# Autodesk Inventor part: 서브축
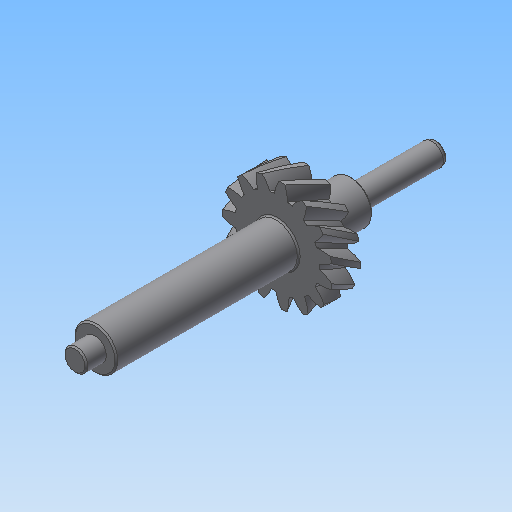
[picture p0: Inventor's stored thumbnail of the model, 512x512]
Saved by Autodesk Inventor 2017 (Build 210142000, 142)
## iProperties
Created: 2016-12
Part Number: 서브축
Material: 강철, 탄소
Document SubType Name: Modeling
Designer: mduedu
Categories: <?xml version="1.0" encoding="UTF-16"?> <MemberInstance><Categories><FamilyTemplate><FamilyTemplateParameter ValueType="xs:double" Id="1" ObjectReferenceKey="da
Density: 7.87 g/cm^3
Appearance: 기본값
Mass: 199.332 g
Surface Area: 86.8151 cm^2
Volume: 25.3281 cm^3
CustomPartVersion: 1
Author: mduedu
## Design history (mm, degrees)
sketch "Sketch1"
  geometry: C1 r 19.321 at (0, 0)
  constraints: 1 centre point
  dimensions: "d0" = 38.64102 diameter of C1 (= da_da)
extrude "Extrusion1" new body sketch "Sketch1" distance "d1" = 10 (= da_b); taper "d2" = 0 deg
workplane "Work Plane2"
sketch "Sketch2"
  geometry: C1 r 19.321 at (0, 0) reference; C2 r 17.321 at (0, 0)
  constraints: 1 centre point, 1 coincident
  dimensions: "d3" = 34.64102 diameter of C2 (= da_dw)
feature "피치 지름" sketch "Sketch2" dims "d4" = 10, "d5" = 0
workplane "Work Plane8"
workplane "Work Plane9"
feature "스퍼 기어" dims "d39" = 0, "da_b" = 10, "da_d" = 34.64102, "da_aw" = 43.87862, "da_da" = 38.64102, "da_df" = 29.64102, "da_dw" = 34.64102, angle "da_beta" = 30 deg, "da_lefttooth" = 0, "da_righttooth" = 10
sketch "스케치3"
  geometry: C1 r 7.5 at (0, 0); 1 further point
  constraints: 1 centre point, 1 coincident
  dimensions: "d49" = 15 diameter of C1
extrude "돌출2" join sketch "스케치3" distance "d50" = 64; taper "d51" = 0 deg
sketch "스케치4"
  geometry: C1 r 4 at (0, 0); 1 further point
  constraints: 1 centre point, 1 coincident
  dimensions: "d52" = 8 diameter of C1
extrude "돌출3" join sketch "스케치4" distance "d53" = 7; taper "d54" = 0 deg
sketch "스케치5"
  geometry: C1 r 7.5 at (0, 0) reference; 1 further point
extrude "돌출4" join sketch "스케치5" distance "d55" = 16; taper "d56" = 0 deg
sketch "스케치6"
  geometry: C1 r 4 at (0, 0); 1 further point
  constraints: 1 centre point, 1 coincident
  dimensions: "d57" = 8 diameter of C1
extrude "돌출5" join sketch "스케치6" distance "d58" = 30; taper "d59" = 0 deg
chamfer "모따기1" distance "d60" = 0.5; stored, may be unused: second distance "d61" = 2, angle "d62" = 45 deg
fillet "모깎기1" dims "d63" = 0.5
sketch "스케치7"
  geometry: L1 (-4, -46)-(4, -46) reference; L2 (4, -16)-(4, -46) reference; L3 (3.3, -46)-(4, -44.788); L4 (0, -46)-(0, 0)
  constraints: 4 end point, 2 point on line, 1 midpoint, 1 parallel
  dimensions: "d64" = 6.6 diameter of L3.start L4; "d65" = 30 deg angle of L2 L3
revolve "회전1" sketch "스케치7" stored, may be unused: angle "d66" = 90 deg
fillet "모깎기2" dims "d67" = 2, "d68" = 1
body "Solid1"
body "Srf1"
other parameters: "d16" = 43.87862 (= da_aw), "d17" = 0, "d34" = 12 deg (computed from da_z), "d41" = 0, "d43" = 43.87862 (= da_aw), "d46" = 43.87862 (= da_aw), "d47" = 0, "d48" = 0
